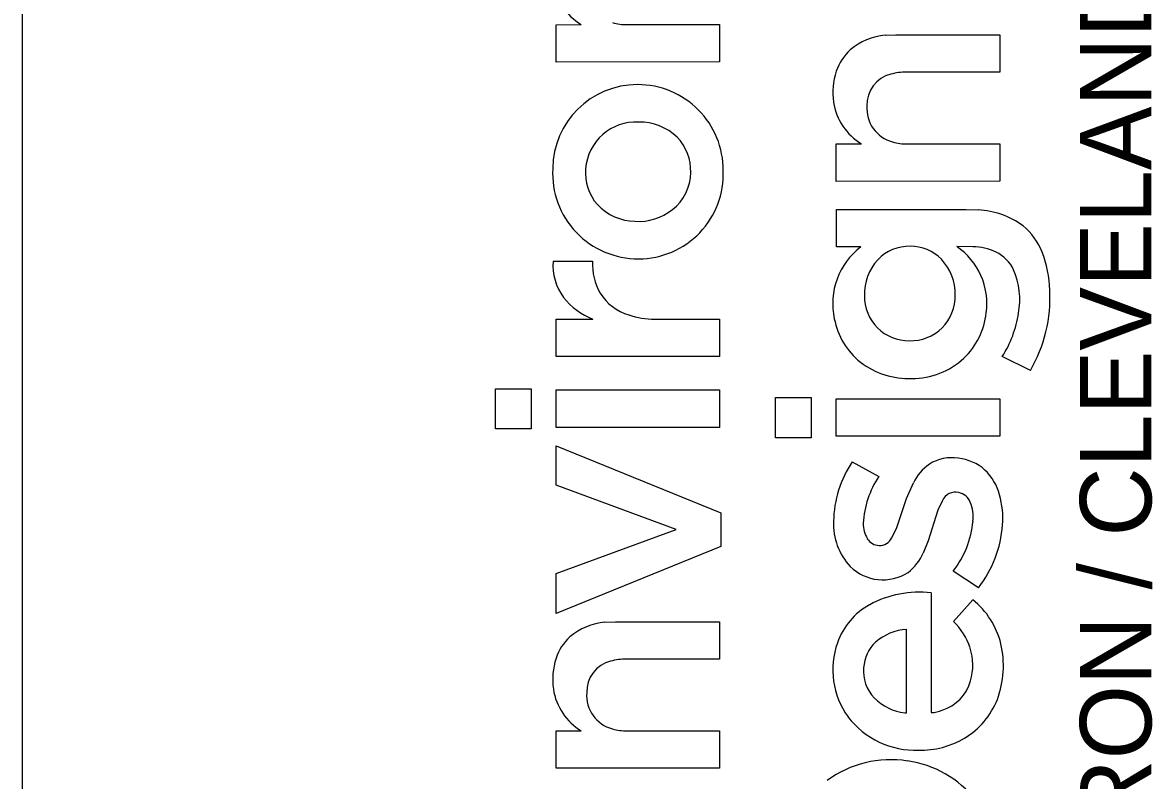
# Model space of a CAD drawing. Extents: x -0.2 to 34, y 0 to 22.
# Drawn here: x 32 to 32.901, y 2.778 to 3.382 of the extents above; entities that cross this region are included whole.
import ezdxf

# ---------------------------------------------------------------- set-up
doc = ezdxf.new("R2010")
doc.units = 0
doc.layers.add('SH_Border', color=7, linetype='Continuous')
doc.layers.add('SH_Data', color=7, linetype='Continuous')

msp = doc.modelspace()

# ---------------------------------------------------------------- linework, layer by layer
at = {"layer": 'SH_Border'}
msp.add_line((32, 0.5), (32, 21.5), dxfattribs=at)
at = {"layer": 'SH_Data'}
for p, q in [((32.42542, 3.38066), (32.44552, 3.38071)), ((32.42542, 3.35086), (32.42542, 3.38066)), ((32.48222, 3.38071), (32.55569, 3.38071)), ((32.55569, 3.38071), (32.55571, 3.35096)), ((32.68784, 3.3722), (32.69634, 3.37266)), ((32.69634, 3.37266), (32.77916, 3.37266)), ((32.77916, 3.37266), (32.77917, 3.34287)), ((32.55571, 3.35096), (32.42542, 3.35086)), ((32.77917, 3.34287), (32.70485, 3.3428)), ((32.64888, 3.2855), (32.66897, 3.28555)), ((32.64888, 3.25569), (32.64888, 3.2855)), ((32.70568, 3.28555), (32.77915, 3.28555)), ((32.77915, 3.28555), (32.77917, 3.25579)), ((32.77917, 3.25579), (32.64888, 3.25569)), ((32.6489, 3.20336), (32.64889, 3.23322)), ((32.64889, 3.23322), (32.75236, 3.23322)), ((32.75236, 3.23322), (32.76191, 3.23285)), ((32.66836, 3.20336), (32.6489, 3.20336)), ((32.75763, 3.20356), (32.74487, 3.20361)), ((32.42299, 3.19193), (32.45454, 3.19193)), ((32.42542, 3.14577), (32.45473, 3.14579)), ((32.42542, 3.11593), (32.42542, 3.14577)), ((32.50413, 3.14581), (32.55571, 3.14573)), ((32.55571, 3.14573), (32.55565, 3.11593)), ((32.55565, 3.11593), (32.42542, 3.11593)), ((32.8036, 3.10491), (32.7812, 3.11598)), ((32.37705, 3.05818), (32.37705, 3.09026)), ((32.37705, 3.09026), (32.40543, 3.09026)), ((32.40543, 3.09026), (32.40543, 3.05818)), ((32.42542, 3.05942), (32.42542, 3.08928)), ((32.42542, 3.08928), (32.55571, 3.08928)), ((32.55571, 3.08928), (32.55571, 3.05942)), ((32.60051, 3.05111), (32.60051, 3.08319)), ((32.60051, 3.08319), (32.62889, 3.08319)), ((32.62889, 3.08319), (32.62889, 3.05111)), ((32.64888, 3.05234), (32.64888, 3.0822)), ((32.64888, 3.0822), (32.77917, 3.0822)), ((32.77917, 3.0822), (32.77917, 3.05234)), ((32.40543, 3.05818), (32.37705, 3.05818)), ((32.55571, 3.05942), (32.42542, 3.05942)), ((32.62889, 3.05111), (32.60051, 3.05111)), ((32.77917, 3.05234), (32.64888, 3.05234)), ((32.42542, 3.01327), (32.42542, 3.0446)), ((32.42542, 3.0446), (32.5567, 2.9913)), ((32.66151, 3.03207), (32.68268, 3.02025)), ((32.52117, 2.97798), (32.42542, 3.01327)), ((32.70483, 3.00258), (32.71036, 3.01526)), ((32.69675, 2.97868), (32.70483, 3.00258)), ((32.73342, 3.00101), (32.72985, 2.9933)), ((32.5567, 2.9913), (32.5567, 2.96441)), ((32.72985, 2.9933), (32.72213, 2.96882)), ((32.42542, 2.94294), (32.52117, 2.97798)), ((32.69299, 2.97117), (32.69675, 2.97868)), ((32.5567, 2.96441), (32.42542, 2.91086)), ((32.72213, 2.96882), (32.71822, 2.95921)), ((32.42542, 2.91086), (32.42542, 2.94294)), ((32.76214, 2.93141), (32.74198, 2.94469)), ((32.72453, 2.92747), (32.72463, 2.83195)), ((32.74228, 2.90465), (32.75768, 2.922)), ((32.46439, 2.90397), (32.47289, 2.90443)), ((32.47289, 2.90443), (32.55571, 2.90443)), ((32.55571, 2.90443), (32.55571, 2.87465)), ((32.70489, 2.83182), (32.70489, 2.89834)), ((32.55571, 2.87465), (32.4814, 2.87457)), ((32.70361, 2.83165), (32.70489, 2.83182)), ((32.42542, 2.81728), (32.44552, 2.81733)), ((32.42542, 2.78747), (32.42542, 2.81728)), ((32.48222, 2.81733), (32.55569, 2.81733)), ((32.55569, 2.81733), (32.55571, 2.78756)), ((32.55571, 2.78756), (32.42542, 2.78747))]:
    msp.add_line(p, q, dxfattribs=at)
for points in [[(32.42542, 3.35086), (32.42542, 3.38066), (32.44552, 3.38071)], [(32.48222, 3.38071), (32.55569, 3.38071), (32.55571, 3.35096), (32.42542, 3.35086)], [(32.68784, 3.3722), (32.69634, 3.37266), (32.77916, 3.37266), (32.77917, 3.34287), (32.70485, 3.3428)], [(32.64888, 3.25569), (32.64888, 3.2855), (32.66897, 3.28555)], [(32.70568, 3.28555), (32.77915, 3.28555), (32.77917, 3.25579), (32.64888, 3.25569)], [(32.66836, 3.20336), (32.6489, 3.20336), (32.64889, 3.23322), (32.75236, 3.23322), (32.76191, 3.23285)], [(32.75763, 3.20356), (32.74487, 3.20361)], [(32.42299, 3.19193), (32.45454, 3.19193)], [(32.50413, 3.14581), (32.55571, 3.14573), (32.55565, 3.11593), (32.42542, 3.11593)], [(32.42542, 3.11593), (32.42542, 3.14577), (32.45473, 3.14579)], [(32.8036, 3.10491), (32.7812, 3.11598)], [(32.66151, 3.03207), (32.68268, 3.02025)], [(32.69299, 2.97117), (32.69675, 2.97868), (32.70483, 3.00258), (32.71036, 3.01526)], [(32.73342, 3.00101), (32.72985, 2.9933), (32.72213, 2.96882), (32.71822, 2.95921)], [(32.76214, 2.93141), (32.74198, 2.94469)], [(32.72453, 2.92747), (32.72463, 2.83195)], [(32.74228, 2.90465), (32.75768, 2.922)], [(32.46439, 2.90397), (32.47289, 2.90443), (32.55571, 2.90443), (32.55571, 2.87465), (32.4814, 2.87457)], [(32.70361, 2.83165), (32.70489, 2.83182), (32.70489, 2.89834)], [(32.42542, 2.78747), (32.42542, 2.81728), (32.44552, 2.81733)], [(32.48222, 2.81733), (32.55569, 2.81733), (32.55571, 2.78756), (32.42542, 2.78747)]]:
    msp.add_lwpolyline(points, dxfattribs=at)
for points in [[(32.37705, 3.05818), (32.37705, 3.09026), (32.40543, 3.09026), (32.40543, 3.05818)], [(32.42542, 3.05942), (32.42542, 3.08928), (32.55571, 3.08928), (32.55571, 3.05942)], [(32.60051, 3.05111), (32.60051, 3.08319), (32.62889, 3.08319), (32.62889, 3.05111)], [(32.64888, 3.05234), (32.64888, 3.0822), (32.77917, 3.0822), (32.77917, 3.05234)], [(32.42542, 2.91086), (32.42542, 2.94294), (32.52117, 2.97798), (32.42542, 3.01327), (32.42542, 3.0446), (32.5567, 2.9913), (32.5567, 2.96441)]]:
    msp.add_lwpolyline(points, close=True, dxfattribs=at)
for centre, radius, start, end in [((32.47027, 3.42141), 0.04763, 188.96462, 238.69865), ((32.47027, 3.42141), 0.04763, 188.96462, 238.69865), ((32.48183, 3.42286), 0.04215, 254.08913, 270.52838), ((32.48183, 3.42286), 0.04215, 254.08913, 270.52838), ((32.69216, 3.32251), 0.04988, 94.97056, 130.22484), ((32.69216, 3.32251), 0.04988, 94.97056, 130.22484), ((32.68694, 3.33085), 0.04016, 132.22383, 161.68229), ((32.68694, 3.33085), 0.04016, 132.22383, 161.68229), ((32.70217, 3.32642), 0.05602, 162.27398, 187.79173), ((32.70217, 3.32642), 0.05602, 162.27398, 187.79173), ((32.70453, 3.29679), 0.04601, 89.60515, 105.33026), ((32.70453, 3.29679), 0.04601, 89.60515, 105.33026), ((32.69828, 3.31689), 0.02498, 103.68683, 182.21395), ((32.69828, 3.31689), 0.02498, 103.68683, 182.21395), ((32.49014, 3.26543), 0.0674, 89.84756, 179.64047), ((32.49014, 3.26543), 0.0674, 89.84756, 179.64047), ((32.49057, 3.26474), 0.0681, 359.54009, 90.21138), ((32.49057, 3.26474), 0.0681, 359.54009, 90.21138), ((32.69372, 3.32624), 0.04763, 188.96462, 238.69865), ((32.69372, 3.32624), 0.04763, 188.96462, 238.69865), ((32.7008, 3.31381), 0.02757, 175.58441, 255.13816), ((32.7008, 3.31381), 0.02757, 175.58441, 255.13816), ((32.48923, 3.26263), 0.0404, 87.04809, 175.57259), ((32.48923, 3.26263), 0.0404, 87.04809, 175.57259), ((32.49204, 3.25999), 0.04299, 45.84264, 90.98008), ((32.49204, 3.25999), 0.04299, 45.84264, 90.98008), ((32.49458, 3.26421), 0.03821, 357.88569, 44.15902), ((32.49458, 3.26421), 0.03821, 357.88569, 44.15902), ((32.70529, 3.32769), 0.04215, 254.08913, 270.52838), ((32.70529, 3.32769), 0.04215, 254.08913, 270.52838), ((32.49083, 3.26209), 0.06819, 176.8344, 270.40384), ((32.49083, 3.26209), 0.06819, 176.8344, 270.40384), ((32.48729, 3.2625), 0.03848, 175.15378, 221.14706), ((32.48729, 3.2625), 0.03848, 175.15378, 221.14706), ((32.49123, 3.26139), 0.06749, 270.06243, 2.37759), ((32.49123, 3.26139), 0.06749, 270.06243, 2.37759), ((32.49446, 3.26318), 0.0383, 308.28936, 359.43468), ((32.49446, 3.26318), 0.0383, 308.28936, 359.43468), ((32.48919, 3.26607), 0.04228, 223.09994, 268.80895), ((32.48919, 3.26607), 0.04228, 223.09994, 268.80895), ((32.49096, 3.2679), 0.04418, 266.56515, 308.06078), ((32.49096, 3.2679), 0.04418, 266.56515, 308.06078), ((32.75907, 3.16789), 0.06503, 53.40344, 87.49062), ((32.75907, 3.16789), 0.06503, 53.40344, 87.49062), ((32.76517, 3.18039), 0.05141, 21.60748, 50.5577), ((32.76517, 3.18039), 0.05141, 21.60748, 50.5577), ((32.70292, 3.15813), 0.05692, 127.37482, 192.22468), ((32.70292, 3.15813), 0.05692, 127.37482, 192.22468), ((32.70693, 3.16927), 0.0346, 88.47302, 136.42562), ((32.70693, 3.16927), 0.0346, 88.47302, 136.42562), ((32.70814, 3.16963), 0.03424, 44.27195, 90.47623), ((32.70814, 3.16963), 0.03424, 44.27195, 90.47623), ((32.71421, 3.15829), 0.05472, 352.1125, 55.92295), ((32.71421, 3.15829), 0.05472, 352.1125, 55.92295), ((32.75666, 3.15725), 0.04633, 65.01687, 88.8011), ((32.75666, 3.15725), 0.04633, 65.01687, 88.8011), ((32.7626, 3.17155), 0.03085, 26.26808, 63.80301), ((32.7626, 3.17155), 0.03085, 26.26808, 63.80301), ((32.73069, 3.16714), 0.08835, 1.15143, 21.3627), ((32.73069, 3.16714), 0.08835, 1.15143, 21.3627), ((32.46616, 3.18882), 0.04329, 175.87313, 216.34747), ((32.46616, 3.18882), 0.04329, 175.87313, 216.34747), ((32.50087, 3.18948), 0.04639, 176.9688, 209.60636), ((32.50087, 3.18948), 0.04639, 176.9688, 209.60636), ((32.71141, 3.16602), 0.0401, 137.46739, 182.33237), ((32.71141, 3.16602), 0.0401, 137.46739, 182.33237), ((32.70368, 3.166), 0.03996, 358.57141, 43.53765), ((32.70368, 3.166), 0.03996, 358.57141, 43.53765), ((32.73565, 3.16154), 0.05953, 349.30734, 23.43071), ((32.73565, 3.16154), 0.05953, 349.30734, 23.43071), ((32.47466, 3.19716), 0.05511, 218.09809, 248.7907), ((32.47466, 3.19716), 0.05511, 218.09809, 248.7907), ((32.49514, 3.18814), 0.04079, 211.94466, 253.2028), ((32.49514, 3.18814), 0.04079, 211.94466, 253.2028), ((32.70645, 3.1637), 0.03511, 178.88208, 271.08374), ((32.70645, 3.1637), 0.03511, 178.88208, 271.08374), ((32.70818, 3.16404), 0.03546, 268.27882, 1.55016), ((32.70818, 3.16404), 0.03546, 268.27882, 1.55016), ((32.70538, 3.16244), 0.11383, 329.6388, 3.25998), ((32.70538, 3.16244), 0.11383, 329.6388, 3.25998), ((32.50465, 3.2165), 0.07069, 252.46555, 269.57296), ((32.50465, 3.2165), 0.07069, 252.46555, 269.57296), ((32.70463, 3.15696), 0.05837, 190.75182, 231.28919), ((32.70463, 3.15696), 0.05837, 190.75182, 231.28919), ((32.70988, 3.15708), 0.05887, 313.74196, 353.8554), ((32.70988, 3.15708), 0.05887, 313.74196, 353.8554), ((32.70738, 3.16334), 0.08771, 327.31495, 351.57478), ((32.70738, 3.16334), 0.08771, 327.31495, 351.57478), ((32.70632, 3.16112), 0.06269, 232.46061, 272.59022), ((32.70632, 3.16112), 0.06269, 232.46061, 272.59022), ((32.70954, 3.15901), 0.06051, 269.6361, 312.70877), ((32.70954, 3.15901), 0.06051, 269.6361, 312.70877), ((32.73636, 2.98258), 0.08973, 146.53104, 178.7571), ((32.73636, 2.98258), 0.08973, 146.53104, 178.7571), ((32.74661, 2.99713), 0.04053, 125.51182, 153.41595), ((32.74661, 2.99713), 0.04053, 125.51182, 153.41595), ((32.7406, 3.0026), 0.03263, 80.17192, 122.51969), ((32.7406, 3.0026), 0.03263, 80.17192, 122.51969), ((32.74278, 2.99824), 0.03667, 47.79344, 84.68918), ((32.74278, 2.99824), 0.03667, 47.79344, 84.68918), ((32.74519, 2.9789), 0.07495, 146.51121, 176.91007), ((32.74519, 2.9789), 0.07495, 146.51121, 176.91007), ((32.73788, 2.9946), 0.04267, 14.9966, 46.20632), ((32.73788, 2.9946), 0.04267, 14.9966, 46.20632), ((32.74384, 2.99631), 0.01143, 76.66094, 155.7053), ((32.74384, 2.99631), 0.01143, 76.66094, 155.7053), ((32.74397, 2.99511), 0.01256, 21.5098, 78.52618), ((32.74397, 2.99511), 0.01256, 21.5098, 78.52618), ((32.71044, 2.98674), 0.07121, 355.83062, 15.39138), ((32.71044, 2.98674), 0.07121, 355.83062, 15.39138), ((32.72592, 2.98766), 0.03209, 354.57264, 22.06805), ((32.72592, 2.98766), 0.03209, 354.57264, 22.06805), ((32.69666, 2.98238), 0.05005, 177.53659, 222.79318), ((32.69666, 2.98238), 0.05005, 177.53659, 222.79318), ((32.6931, 2.98233), 0.02276, 178.47474, 211.08679), ((32.6931, 2.98233), 0.02276, 178.47474, 211.08679), ((32.68248, 2.99149), 0.0757, 321.81101, 354.79685), ((32.68248, 2.99149), 0.0757, 321.81101, 354.79685), ((32.68952, 2.9882), 0.09219, 321.9777, 355.87384), ((32.68952, 2.9882), 0.09219, 321.9777, 355.87384), ((32.68331, 2.9767), 0.01148, 212.23676, 268.37769), ((32.68331, 2.9767), 0.01148, 212.23676, 268.37769), ((32.68342, 2.97589), 0.01067, 267.71603, 333.73375), ((32.68342, 2.97589), 0.01067, 267.71603, 333.73375), ((32.68098, 2.9758), 0.04077, 308.08772, 335.98736), ((32.68098, 2.9758), 0.04077, 308.08772, 335.98736), ((32.68599, 2.97535), 0.0375, 225.98539, 302.47965), ((32.68599, 2.97535), 0.0375, 225.98539, 302.47965), ((32.7152, 2.84414), 0.08384, 83.61499, 118.28755), ((32.7152, 2.84414), 0.08384, 83.61499, 118.28755), ((32.71744, 2.87167), 0.06443, 13.53365, 51.36148), ((32.71744, 2.87167), 0.06443, 13.53365, 51.36148), ((32.70239, 2.86906), 0.05583, 118.83082, 160.62438), ((32.70239, 2.86906), 0.05583, 118.83082, 160.62438), ((32.46871, 2.85428), 0.04988, 94.96958, 130.22249), ((32.46871, 2.85428), 0.04988, 94.96958, 130.22249), ((32.70378, 2.86556), 0.05486, 19.03571, 45.44059), ((32.70378, 2.86556), 0.05486, 19.03571, 45.44059), ((32.46348, 2.86263), 0.04015, 132.22192, 161.68183), ((32.46348, 2.86263), 0.04015, 132.22192, 161.68183), ((32.70785, 2.85609), 0.04235, 94.00805, 130.88169), ((32.70785, 2.85609), 0.04235, 94.00805, 130.88169), ((32.71041, 2.86612), 0.06437, 160.52012, 215.78311), ((32.71041, 2.86612), 0.06437, 160.52012, 215.78311), ((32.70048, 2.86628), 0.02985, 132.98507, 177.179), ((32.70048, 2.86628), 0.02985, 132.98507, 177.179), ((32.71069, 2.8697), 0.047, 344.60586, 17.007), ((32.71069, 2.8697), 0.047, 344.60586, 17.007), ((32.70635, 2.86921), 0.07579, 339.3542, 13.37853), ((32.70635, 2.86921), 0.07579, 339.3542, 13.37853), ((32.47872, 2.85819), 0.05601, 162.27355, 187.79185), ((32.47872, 2.85819), 0.05601, 162.27355, 187.79185), ((32.48108, 2.82856), 0.04601, 89.60494, 105.3284), ((32.48108, 2.82856), 0.04601, 89.60494, 105.3284), ((32.47482, 2.84867), 0.02498, 103.68646, 182.21874), ((32.47482, 2.84867), 0.02498, 103.68646, 182.21874), ((32.7017, 2.86503), 0.03115, 175.00126, 223.28301), ((32.7017, 2.86503), 0.03115, 175.00126, 223.28301), ((32.7224, 2.86715), 0.03504, 288.00773, 343.55078), ((32.7224, 2.86715), 0.03504, 288.00773, 343.55078), ((32.47026, 2.85802), 0.04762, 188.96199, 238.70369), ((32.47026, 2.85802), 0.04762, 188.96199, 238.70369), ((32.47735, 2.84558), 0.02756, 175.58538, 255.14386), ((32.47735, 2.84558), 0.02756, 175.58538, 255.14386), ((32.70891, 2.87363), 0.04231, 225.06188, 262.79738), ((32.70891, 2.87363), 0.04231, 225.06188, 262.79738), ((32.71894, 2.8652), 0.0626, 300.94269, 338.73225), ((32.71894, 2.8652), 0.0626, 300.94269, 338.73225), ((32.72474, 2.85216), 0.02021, 269.7003, 294.8711), ((32.72474, 2.85216), 0.02021, 269.7003, 294.8711), ((32.71253, 2.87054), 0.06872, 217.74516, 271.65431), ((32.71253, 2.87054), 0.06872, 217.74516, 271.65431), ((32.48183, 2.85948), 0.04215, 254.09162, 270.52835), ((32.48183, 2.85948), 0.04215, 254.09162, 270.52835), ((32.71549, 2.87241), 0.07056, 269.20477, 300.33412), ((32.71549, 2.87241), 0.07056, 269.20477, 300.33412), ((32.69229, 2.70792), 0.08641, 81.19402, 125.99844), ((32.69229, 2.70792), 0.08641, 81.19402, 125.99844), ((32.69458, 2.71132), 0.08272, 37.85208, 82.40204), ((32.69458, 2.71132), 0.08272, 37.85208, 82.40204)]:
    msp.add_arc(centre, radius, start, end, dxfattribs=at)

# ---------------------------------------------------------------- texts
msp.add_text('AKRON / CLEVELAND / COLUMBUS', height=0.056969, rotation=90, dxfattribs=at).set_placement((32.90012, 2.638))

doc.saveas('drawing.dxf')
